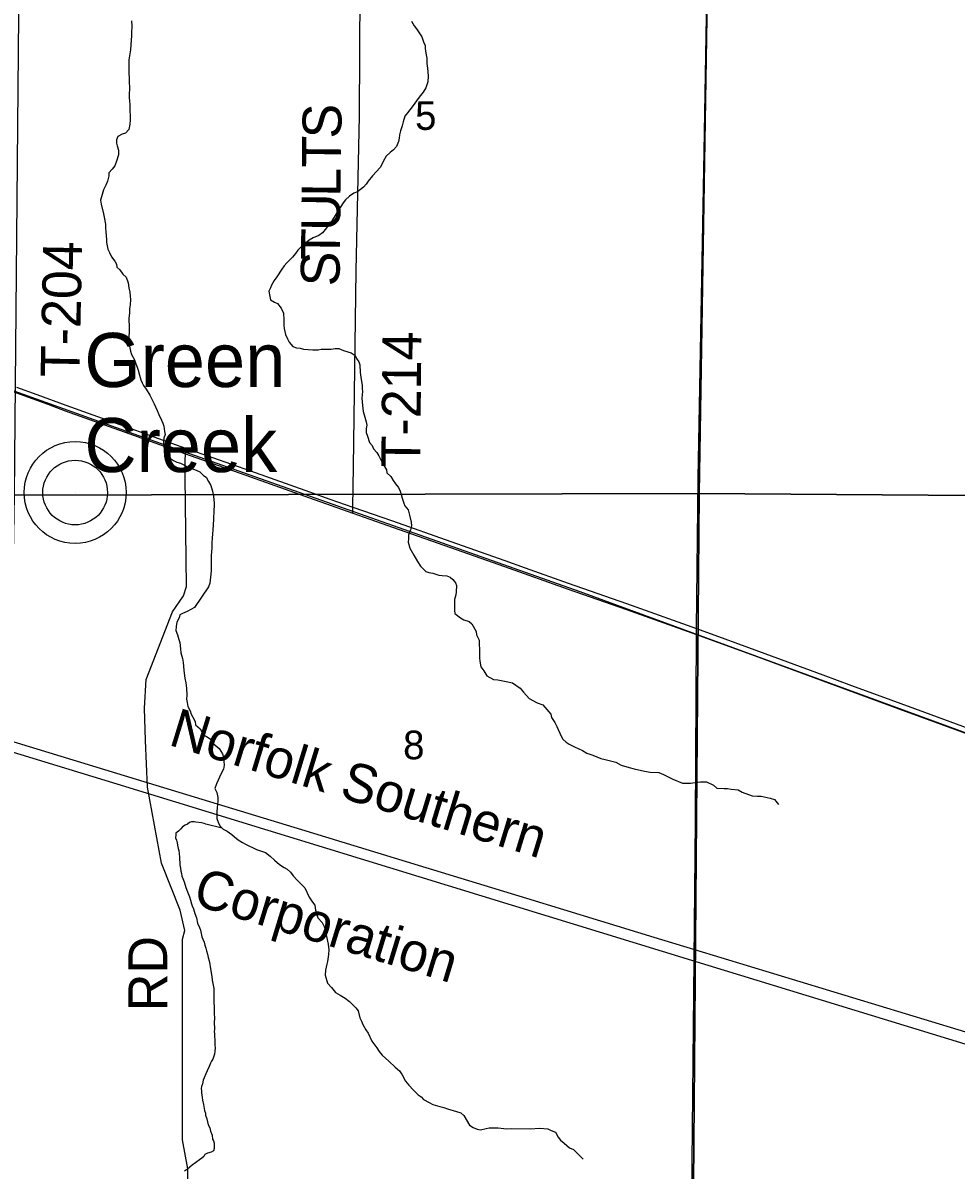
# Model space of a CAD drawing. Extents: x 0 to 34, y 0 to 22.
# Drawn here: x 3.538 to 4.9, y 18.476 to 20.151 of the extents above; entities that cross this region are included whole.
import ezdxf

# ---------------------------------------------------------------- set-up
doc = ezdxf.new("R2010")
doc.units = 0
for name, color, linetype in [('GM_X_Minor_River', 7, 'Continuous'), ('GM_X_Rail_Line', 7, 'Continuous'), ('GM_X_Rail_Line_Text', 7, 'Continuous'), ('GM_X_Section', 7, 'Continuous'), ('GM_X_Section_Text', 7, 'Continuous'), ('GM_X_Township_Road', 7, 'Continuous'), ('GM_X_Township_Road_Text', 7, 'Continuous'), ('GM_X_Unincorporated', 7, 'Continuous'), ('GM_X_Unincorporated_Location', 7, 'Continuous'), ('GM_X_Unincorporated_Text', 7, 'Continuous'), ('GM_X_US_Route', 7, 'Continuous')]:
    doc.layers.add(name, color=color, linetype=linetype)

msp = doc.modelspace()

# ---------------------------------------------------------------- linework, layer by layer
at = {"layer": 'GM_X_Minor_River'}
for points in [[(3.6962, 20.1541), (3.6969, 20.1468), (3.6964, 20.1362), (3.6963, 20.1317), (3.6955, 20.1264), (3.6946, 20.1119), (3.6933, 20.1029), (3.6925, 20.0972), (3.6924, 20.0907), (3.6923, 20.0771), (3.6926, 20.0706), (3.6929, 20.0626), (3.6932, 20.0584), (3.6932, 20.0535), (3.6927, 20.0482), (3.6927, 20.0421), (3.6934, 20.0368), (3.6937, 20.0319), (3.6936, 20.0277), (3.694, 20.0235), (3.6942, 20.0148), (3.6942, 20.0091), (3.6937, 20.003), (3.6921, 19.9954), (3.6875, 19.9898), (3.6826, 19.9883), (3.6764, 19.985), (3.6745, 19.9801), (3.6744, 19.9755), (3.6755, 19.9713), (3.677, 19.9652), (3.6773, 19.9584), (3.6745, 19.9489), (3.6718, 19.9421), (3.6679, 19.9376), (3.6633, 19.932), (3.6629, 19.9278), (3.6613, 19.9199), (3.6586, 19.9142), (3.6551, 19.907), (3.6535, 19.9006), (3.6511, 19.8919), (3.6518, 19.8862), (3.6554, 19.8721), (3.6565, 19.8671), (3.6583, 19.8573), (3.6582, 19.8519), (3.6586, 19.8459), (3.6596, 19.8345), (3.6599, 19.8303), (3.6617, 19.8204), (3.6643, 19.8158), (3.6669, 19.8093), (3.6717, 19.8032), (3.6743, 19.7986), (3.675, 19.7944), (3.6792, 19.7902), (3.6836, 19.7841), (3.6885, 19.7795), (3.6911, 19.7715), (3.6925, 19.7639), (3.6936, 19.7578), (3.6943, 19.7521), (3.6946, 19.7468), (3.6941, 19.7392)], [(4.1051, 20.1538), (4.1092, 20.1466), (4.1122, 20.1424), (4.1152, 20.1378), (4.12, 20.1305), (4.1226, 20.1233), (4.1248, 20.118), (4.1252, 20.1138), (4.1262, 20.1069), (4.1273, 20.0993), (4.1276, 20.0917), (4.1282, 20.0849), (4.1289, 20.0796), (4.1293, 20.0731), (4.1288, 20.0651), (4.126, 20.0564), (4.1222, 20.0497), (4.1164, 20.0425), (4.1125, 20.0372), (4.1075, 20.0304), (4.1025, 20.0241), (4.0991, 20.0195), (4.0952, 20.015), (4.0928, 20.0067), (4.0912, 20.0006), (4.0889, 19.9934), (4.0873, 19.9874), (4.0869, 19.9825), (4.0861, 19.9779), (4.0833, 19.9707), (4.0787, 19.9655), (4.0737, 19.9617), (4.068, 19.9565), (4.0637, 19.9485), (4.0618, 19.944), (4.0594, 19.9399), (4.0479, 19.9278), (4.0418, 19.9199), (4.0391, 19.9154), (4.0352, 19.9109), (4.0306, 19.9079), (4.026, 19.9042), (4.0211, 19.9023), (4.0146, 19.8982), (4.0088, 19.8926), (4.0054, 19.8881)], [(4.0054, 19.8881), (4.0019, 19.8828), (3.9984, 19.8779), (3.9953, 19.8722), (3.9884, 19.8609), (3.9841, 19.8556), (3.9811, 19.8515), (3.9749, 19.8444), (3.9696, 19.8406), (3.9615, 19.8369), (3.9554, 19.8336), (3.9501, 19.8294), (3.9459, 19.8261), (3.9393, 19.8193), (3.9355, 19.814), (3.9313, 19.8088), (3.9267, 19.8046), (3.9232, 19.8005), (3.9193, 19.796), (3.9159, 19.7915), (3.9085, 19.7802), (3.9047, 19.7749), (3.9008, 19.7681), (3.8993, 19.7639), (3.8969, 19.759), (3.8984, 19.7514), (3.8994, 19.7465), (3.9051, 19.743), (3.9096, 19.7411), (3.9148, 19.7342), (3.9182, 19.7269), (3.9188, 19.7174), (3.9184, 19.7094), (3.9191, 19.7045), (3.9212, 19.6961), (3.9242, 19.6896), (3.9264, 19.6847), (3.932, 19.6786), (3.9373, 19.6766), (3.9423, 19.6758), (3.9476, 19.6746), (3.9608, 19.6733), (3.9688, 19.6736), (3.973, 19.6743), (3.9771, 19.6747), (3.9878, 19.6745), (3.9935, 19.6756), (3.9988, 19.6756), (4.0056, 19.6724), (4.0169, 19.6689), (4.0226, 19.6651), (4.0248, 19.6609), (4.0281, 19.6559), (4.0296, 19.6517), (4.0302, 19.6403), (4.0316, 19.63), (4.0331, 19.622), (4.033, 19.6167), (4.0333, 19.6126), (4.0329, 19.608), (4.0325, 19.6027), (4.0328, 19.5978), (4.0335, 19.5924), (4.0345, 19.5833), (4.0367, 19.5753), (4.0389, 19.5685), (4.0396, 19.5635), (4.0388, 19.5586), (4.0391, 19.5529), (4.0406, 19.5472), (4.0439, 19.538), (4.0476, 19.5338), (4.0498, 19.5289), (4.0543, 19.5235), (4.0573, 19.5189), (4.0599, 19.514), (4.0629, 19.5079), (4.0684, 19.4983), (4.0691, 19.4937), (4.0748, 19.4884), (4.0785, 19.4826), (4.0819, 19.4777), (4.086, 19.4723), (4.0886, 19.4673), (4.09, 19.4624), (4.0915, 19.4571), (4.0937, 19.4498), (4.0955, 19.4456), (4.1, 19.4399), (4.1022, 19.4319), (4.1044, 19.422), (4.1051, 19.4167), (4.1035, 19.4106), (4.1007, 19.4027), (4.1007, 19.3977), (4.1002, 19.3928), (4.1024, 19.3837), (4.1084, 19.3734), (4.1136, 19.3646), (4.1184, 19.3577), (4.1259, 19.3496)], [(3.6941, 19.7392), (3.6933, 19.7335), (3.6932, 19.7274), (3.6924, 19.7191), (3.6926, 19.7062), (3.6924, 19.6864), (3.6931, 19.6788), (3.6945, 19.6716), (3.6963, 19.6667), (3.7004, 19.6587), (3.7023, 19.6533), (3.7045, 19.648), (3.7059, 19.6438), (3.7078, 19.6366), (3.7096, 19.6297), (3.7118, 19.6255), (3.7136, 19.6213), (3.7178, 19.616), (3.723, 19.6072), (3.7263, 19.6007), (3.7293, 19.5946), (3.7311, 19.5904), (3.7337, 19.5847), (3.7359, 19.5789), (3.74, 19.5709), (3.7418, 19.5663), (3.7433, 19.5622), (3.7444, 19.5542), (3.7455, 19.55), (3.7435, 19.5443), (3.743, 19.5363), (3.7441, 19.5291), (3.7448, 19.5246), (3.7478, 19.5192), (3.7519, 19.5158), (3.7575, 19.5119), (3.7624, 19.5096), (3.7677, 19.508), (3.7734, 19.5049), (3.7798, 19.501), (3.7843, 19.5002), (3.7908, 19.4979), (3.796, 19.4955), (3.8013, 19.4902), (3.8054, 19.4875), (3.8088, 19.4814), (3.8121, 19.4753), (3.8147, 19.4669), (3.8157, 19.46), (3.8168, 19.4498), (3.8167, 19.4456), (3.8163, 19.4395), (3.8161, 19.4255), (3.8156, 19.4183), (3.8148, 19.4099), (3.8144, 19.4054), (3.8139, 19.3978), (3.8134, 19.3921), (3.8134, 19.3845), (3.8129, 19.3784), (3.8125, 19.3731), (3.8124, 19.3682), (3.8127, 19.3614), (3.8126, 19.3507), (3.8117, 19.3413), (3.8105, 19.3325), (3.8085, 19.3273)], [(4.1259, 19.3496), (4.1305, 19.3485), (4.1361, 19.3473), (4.1407, 19.3457), (4.1452, 19.3445), (4.1497, 19.3437), (4.1566, 19.3432), (4.1615, 19.3413), (4.1656, 19.3382), (4.1694, 19.3332), (4.1708, 19.3291), (4.1703, 19.3199), (4.1699, 19.3158), (4.1679, 19.309), (4.1678, 19.293), (4.1681, 19.2885), (4.1764, 19.2823), (4.1816, 19.2792), (4.1892, 19.2768), (4.1933, 19.2734), (4.1996, 19.2619), (4.2, 19.2574), (4.2037, 19.2497), (4.204, 19.2452), (4.2043, 19.2346), (4.2046, 19.2292), (4.2045, 19.2239), (4.2048, 19.2186), (4.2063, 19.2106), (4.2108, 19.2049), (4.2152, 19.1972), (4.225, 19.1922), (4.2311, 19.1914), (4.2432, 19.189), (4.2527, 19.187), (4.2639, 19.1796), (4.2688, 19.1735), (4.2771, 19.1643), (4.2887, 19.1581), (4.2967, 19.155), (4.3086, 19.1412), (4.3097, 19.1366), (4.3142, 19.1294), (4.3175, 19.1233), (4.3238, 19.1092), (4.3261, 19.1049), (4.3309, 19.1003), (4.3351, 19.0976), (4.34, 19.0953), (4.3441, 19.0934), (4.3483, 19.0914), (4.3547, 19.0883), (4.3611, 19.0845), (4.3653, 19.0829), (4.3698, 19.0813), (4.3815, 19.0766), (4.3879, 19.0754), (4.4034, 19.0711), (4.4114, 19.0668), (4.4227, 19.0637), (4.4303, 19.0617), (4.4454, 19.0581), (4.4537, 19.0569), (4.4662, 19.056), (4.473, 19.0533), (4.4866, 19.0463), (4.501, 19.0404), (4.5123, 19.0407), (4.523, 19.0421), (4.5272, 19.0428), (4.5359, 19.0427), (4.5461, 19.0377), (4.5509, 19.0335), (4.5616, 19.033), (4.5665, 19.0329), (4.5718, 19.0317), (4.582, 19.0308), (4.5877, 19.0274), (4.6024, 19.0223), (4.6104, 19.0218), (4.6157, 19.0217), (4.6289, 19.0189), (4.635, 19.017), (4.641, 19.0093)], [(3.8085, 19.3273), (3.7881, 19.2971), (3.7774, 19.2911), (3.7709, 19.2886), (3.7667, 19.2867), (3.7659, 19.2822), (3.7624, 19.2757), (3.7612, 19.2693), (3.7611, 19.2636), (3.7634, 19.2575), (3.7655, 19.2503), (3.7666, 19.2461), (3.7677, 19.2366), (3.768, 19.2309), (3.7705, 19.2229), (3.7716, 19.2168), (3.7719, 19.2115), (3.7726, 19.205), (3.774, 19.194), (3.7754, 19.1872), (3.7765, 19.1792), (3.7768, 19.1693), (3.7763, 19.1632), (3.7774, 19.1583), (3.7785, 19.1526), (3.7818, 19.1465), (3.7833, 19.1415), (3.7859, 19.1369), (3.7892, 19.1305), (3.7895, 19.1259), (3.7963, 19.1198), (3.8011, 19.1114), (3.8057, 19.1086), (3.8113, 19.1056), (3.8154, 19.0987), (3.824, 19.0914), (3.8289, 19.0837), (3.8307, 19.0788), (3.8314, 19.067), (3.8305, 19.0613), (3.827, 19.0549), (3.8204, 19.0394), (3.8181, 19.033), (3.821, 19.0269), (3.8225, 19.0196), (3.8224, 19.0143), (3.822, 19.0094), (3.8212, 19.0045), (3.8207, 18.9992), (3.8207, 18.9939), (3.821, 18.9889), (3.8228, 18.9836), (3.8254, 18.9782), (3.8299, 18.9733), (3.8359, 18.9705), (3.8427, 18.9655), (3.8468, 18.9624), (3.8521, 18.9578), (3.8581, 18.954), (3.8638, 18.9509), (3.8687, 18.9486), (3.8728, 18.9466), (3.8789, 18.9439), (3.8861, 18.9415), (3.8917, 18.9392), (3.8989, 18.9338), (3.9049, 18.928), (3.9124, 18.9219), (3.9192, 18.9176), (3.9233, 18.9149), (3.9282, 18.9107), (3.9323, 18.9054), (3.9379, 18.8988), (3.9432, 18.8939), (3.9495, 18.8877), (3.9558, 18.874), (3.9607, 18.8667), (3.9637, 18.8625), (3.9647, 18.8549), (3.9662, 18.85), (3.9684, 18.8439), (3.9748, 18.8373), (3.9777, 18.8312), (3.9796, 18.8248), (3.981, 18.8168), (3.9835, 18.8057), (3.9842, 18.797), (3.9837, 18.7906), (3.9825, 18.7803), (3.9813, 18.7762), (3.9793, 18.7674), (3.9788, 18.7602), (3.9825, 18.7484), (3.9881, 18.7423), (3.9941, 18.735), (4.0009, 18.7308), (4.0084, 18.7265), (4.0144, 18.7219), (4.0238, 18.7127), (4.0272, 18.7081), (4.0297, 18.6978)], [(3.8286, 18.9747), (3.8049, 18.9809), (3.8023, 18.9818), (3.7985, 18.9826), (3.7902, 18.9835), (3.7876, 18.9839), (3.7838, 18.984), (3.7811, 18.9833), (3.778, 18.9807), (3.7746, 18.9793), (3.7708, 18.9767), (3.7681, 18.9737), (3.765, 18.9704), (3.7611, 18.9678), (3.7607, 18.9651), (3.7606, 18.961), (3.7617, 18.9575), (3.7627, 18.9537), (3.7634, 18.9499), (3.7641, 18.9453), (3.7655, 18.9423), (3.7658, 18.9373), (3.7664, 18.9324), (3.7664, 18.9298), (3.7666, 18.9244), (3.767, 18.9214), (3.7676, 18.9165), (3.7683, 18.9123), (3.769, 18.9088), (3.7696, 18.9047), (3.7711, 18.9012), (3.7729, 18.8966), (3.7757, 18.8882), (3.7779, 18.8817), (3.7807, 18.8745), (3.7825, 18.8695), (3.7836, 18.8642), (3.7846, 18.8615), (3.7868, 18.8569), (3.7886, 18.8504), (3.7911, 18.8439), (3.7928, 18.8359), (3.7953, 18.8298), (3.7968, 18.826), (3.7988, 18.8164), (3.8003, 18.813), (3.8021, 18.8084), (3.8031, 18.8038), (3.8046, 18.7996), (3.8056, 18.7958), (3.807, 18.7909), (3.808, 18.7859), (3.8095, 18.781), (3.8105, 18.7764), (3.8112, 18.7726), (3.8125, 18.7642), (3.8128, 18.7608), (3.8135, 18.7581), (3.8142, 18.7528), (3.8155, 18.7456), (3.8166, 18.7406), (3.8163, 18.7277), (3.8165, 18.7198), (3.8168, 18.7144), (3.8167, 18.7091), (3.817, 18.7046), (3.8172, 18.697), (3.8171, 18.6917), (3.8172, 18.6814), (3.8171, 18.6776), (3.8175, 18.675), (3.8179, 18.6613), (3.8179, 18.6579), (3.8182, 18.6541), (3.8177, 18.6488), (3.8172, 18.645), (3.8152, 18.6375), (3.8128, 18.6345), (3.8116, 18.6319), (3.8096, 18.6266), (3.8065, 18.6206), (3.8049, 18.6161), (3.8025, 18.61), (3.8009, 18.6067), (3.7997, 18.6017), (3.7984, 18.5976), (3.798, 18.5946), (3.7983, 18.5912), (3.7986, 18.5885), (3.7989, 18.5851), (3.7992, 18.5813), (3.7999, 18.5775), (3.8013, 18.5714), (3.803, 18.5626), (3.8041, 18.5584), (3.8044, 18.5558), (3.8062, 18.5504), (3.8072, 18.5462), (3.8083, 18.5416), (3.8104, 18.5374), (3.8115, 18.5321)], [(4.0297, 18.6978), (4.0319, 18.6932), (4.0338, 18.6883), (4.0386, 18.6803), (4.042, 18.6757), (4.0471, 18.6639), (4.0546, 18.6539), (4.058, 18.6489), (4.0624, 18.6432), (4.0718, 18.6344), (4.0812, 18.6259), (4.0876, 18.6205), (4.0913, 18.6144), (4.0962, 18.6056), (4.1014, 18.5995), (4.1078, 18.5922), (4.1149, 18.5853), (4.119, 18.5826), (4.1224, 18.5784), (4.1307, 18.5741), (4.1363, 18.5714), (4.1462, 18.5683), (4.1522, 18.5671), (4.1575, 18.5651), (4.1707, 18.5612), (4.1772, 18.5592), (4.1817, 18.555), (4.1899, 18.5409), (4.1951, 18.5378), (4.2008, 18.5354), (4.2057, 18.5342), (4.2141, 18.5364), (4.2183, 18.5371), (4.2274, 18.537), (4.2315, 18.5374), (4.2399, 18.5362), (4.2444, 18.5357), (4.2505, 18.536), (4.2786, 18.5357), (4.2919, 18.5367), (4.304, 18.5358), (4.3089, 18.5331), (4.3153, 18.5308), (4.319, 18.5235), (4.3228, 18.5193), (4.328, 18.5147), (4.3359, 18.5078), (4.3416, 18.5058), (4.3513, 18.4959), (4.3558, 18.4916)], [(3.8115, 18.5321), (3.814, 18.5267), (3.8146, 18.5207), (3.8157, 18.518), (3.8168, 18.5149), (3.8167, 18.5115), (3.817, 18.507), (3.8158, 18.5036), (3.8123, 18.5017), (3.807, 18.5003), (3.8032, 18.4981), (3.8016, 18.4955), (3.7989, 18.4929), (3.7955, 18.4907), (3.7847, 18.4826), (3.7781, 18.477), (3.7735, 18.4737)]]:
    msp.add_lwpolyline(points, dxfattribs=at)
at = {"layer": 'GM_X_Rail_Line'}
for points in [[(2.1, 20.1355), (2.5574, 19.9667), (3.1422, 19.7506), (3.6996, 19.5506), (4.3507, 19.3207), (4.9212, 19.1118), (5.8157, 18.7674), (6.212, 18.6139), (6.6644, 18.4531), (7.3247, 18.2205), (7.6757, 18.0934)], [(2.1, 19.5368), (2.1257, 19.529), (2.3297, 19.4665), (2.3712, 19.4537), (2.4946, 19.4156), (2.5895, 19.3868), (2.8189, 19.3166), (2.9839, 19.2661), (3.0893, 19.234), (3.17, 19.2094), (3.2494, 19.1851), (3.3541, 19.1532), (3.437, 19.1279), (3.5117, 19.1049), (3.7206, 19.0413), (3.9442, 18.9731), (4.115, 18.921), (4.2732, 18.8725), (4.3809, 18.8396), (4.4591, 18.8158), (4.5185, 18.7976), (5.0181, 18.6458)], [(2.1, 19.5186), (2.8346, 19.2964), (3.6748, 19.0394), (4.5141, 18.7823), (5.7652, 18.3991), (6.2109, 18.2673), (6.7654, 18.1025), (7.4524, 17.8921)]]:
    msp.add_lwpolyline(points, dxfattribs=at)
at = {"layer": 'GM_X_Section'}
for points in [[(5.5347, 20.4166), (5.5276, 19.4562), (4.5252, 19.4639), (4.5401, 20.4008), (4.5765, 20.4024)], [(4.5401, 20.4008), (4.5252, 19.4639), (3.5253, 19.4614), (3.5337, 20.3786), (3.5682, 20.3787)], [(4.5252, 19.4639), (4.517, 18.4555), (3.5082, 18.4594), (3.5253, 19.4614)], [(5.5276, 19.4562), (5.5161, 18.4568), (4.517, 18.4555), (4.5252, 19.4639)]]:
    msp.add_lwpolyline(points, close=True, dxfattribs=at)
at = {"layer": 'GM_X_Township_Road'}
for p, q in [((4.5325, 19.963), (4.5402, 20.3949)), ((4.5096, 17.9519), (4.5176, 18.7828))]:
    msp.add_line(p, q, dxfattribs=at)
for points in [[(4.0282, 19.9699), (4.0292, 20.0154), (4.0309, 20.3841)], [(4.0194, 19.4351), (4.0196, 19.4438), (4.0206, 19.5032), (4.0244, 19.789), (4.0282, 19.9699)], [(4.5213, 19.2577), (4.5214, 19.2666), (4.5239, 19.4859), (4.5325, 19.963)], [(3.7747, 19.5115), (3.7749, 19.5215), (3.7751, 19.53)], [(3.7195, 19.0346), (3.7168, 19.103), (3.7153, 19.1501), (3.7175, 19.1918), (3.7563, 19.2907), (3.7723, 19.3144), (3.7763, 19.328), (3.7744, 19.4886), (3.7747, 19.5115)], [(4.5176, 18.7828), (4.5196, 18.9856), (4.5213, 19.2577)], [(3.7763, 18.2226), (3.7785, 18.4772), (3.7705, 18.5198), (3.7706, 18.8127), (3.7739, 18.8252), (3.7671, 18.8549), (3.7401, 18.9237), (3.7195, 19.0346)]]:
    msp.add_lwpolyline(points, dxfattribs=at)
at = {"layer": 'GM_X_Unincorporated'}
for radius in [0.0744, 0.0472]:
    msp.add_circle((3.6139, 19.4651), radius, dxfattribs=at)
at = {"layer": 'GM_X_Unincorporated_Location'}
msp.add_line((3.6139, 19.4651), (3.6139, 19.4651), dxfattribs=at)
at = {"layer": 'GM_X_US_Route'}
for points in [[(3.3105, 19.6891), (3.3363, 19.6798), (3.4714, 19.6308), (3.5283, 19.6107), (3.5739, 19.594)], [(3.5284, 19.619), (3.558, 19.6082), (3.6005, 19.5929), (3.6861, 19.5619), (3.7288, 19.5464), (3.7751, 19.53), (3.8144, 19.5161), (3.8701, 19.4967), (3.9561, 19.4662), (3.9858, 19.4556), (4.0196, 19.4438)], [(3.5739, 19.594), (3.5995, 19.5846), (3.6924, 19.5511), (3.7749, 19.5215), (3.87, 19.4879), (3.956, 19.4575), (4.0194, 19.4351)], [(4.0194, 19.4351), (4.0771, 19.4147), (4.1622, 19.3846), (4.2411, 19.3569), (4.3338, 19.3241), (4.4191, 19.2941), (4.5213, 19.2577)], [(4.0196, 19.4438), (4.0772, 19.4236), (4.1623, 19.3934), (4.2412, 19.3657), (4.271, 19.355), (4.3339, 19.3329), (4.4192, 19.303), (4.5214, 19.2666)], [(4.5213, 19.2577), (4.611, 19.225), (4.7241, 19.1834), (4.8167, 19.1493), (4.9089, 19.1155), (4.9868, 19.0868), (5.0221, 19.0739), (5.0434, 19.0662), (5.0859, 19.0504), (5.129, 19.0346), (5.1712, 19.0188), (5.2139, 19.0026), (5.243, 18.9914), (5.2631, 18.9836), (5.34, 18.9532), (5.4317, 18.9169), (5.5303, 18.8776), (5.6144, 18.8443), (5.7056, 18.8082), (5.7275, 18.7993)], [(4.5214, 19.2666), (4.5628, 19.2515), (4.6116, 19.2335), (4.7056, 19.199), (4.7477, 19.1835), (4.805, 19.1625), (4.8542, 19.1444), (4.9095, 19.124), (4.9887, 19.0949), (5.0227, 19.0824), (5.0456, 19.0741), (5.0862, 19.0592), (5.1293, 19.0433), (5.1729, 19.0273), (5.2156, 19.0112), (5.244, 19), (5.2634, 18.9924), (5.3001, 18.9779), (5.3415, 18.9613), (5.4332, 18.9251), (5.5318, 18.8857), (5.6159, 18.8525), (5.7071, 18.8163), (5.729, 18.8075)]]:
    msp.add_lwpolyline(points, dxfattribs=at)

# ---------------------------------------------------------------- texts
at = {"layer": 'GM_X_Rail_Line_Text'}
for s, rotation, p in [('Norfolk Southern', 342.9781, (3.7486, 19.0969)), ('Corporation', 343.0149, (3.7836, 18.8641))]:
    msp.add_text(s, height=0.056629, rotation=rotation, dxfattribs=at).set_placement(p)
at = {"layer": 'GM_X_Section_Text'}
for s, p in [('5', (4.1103, 19.9948)), ('8', (4.0928, 19.0755))]:
    msp.add_text(s, height=0.0419, rotation=0, dxfattribs=at).set_placement(p)
at = {"layer": 'GM_X_Township_Road_Text'}
for s, height, rotation, p in [('S', 0.0568, 88.6124, (4.0022, 19.9817)), ('T', 0.0568, 89.4, (4.0017, 19.9394)), ('L', 0.0568, 89.4257, (4.0013, 19.8969)), ('U', 0.0568, 89.4244, (4.0008, 19.8469)), ('T', 0.0568, 89.4257, (4.0004, 19.8045)), ('T-204', 0.05682, 88.8762, (3.6202, 19.6331)), ('S', 0.0568, 89.4251, (4, 19.7661)), ('T-214', 0.05682, 89.4386, (4.1177, 19.5016)), ('RD', 0.05682, 90, (3.7484, 18.7076))]:
    msp.add_text(s, height=height, rotation=rotation, dxfattribs=at).set_placement(p)
at = {"layer": 'GM_X_Unincorporated_Text'}
for s, p in [('Green', (3.6274, 19.6192)), ('Creek', (3.6274, 19.495))]:
    msp.add_text(s, height=0.07898, rotation=0, dxfattribs=at).set_placement(p)

doc.saveas('drawing.dxf')
